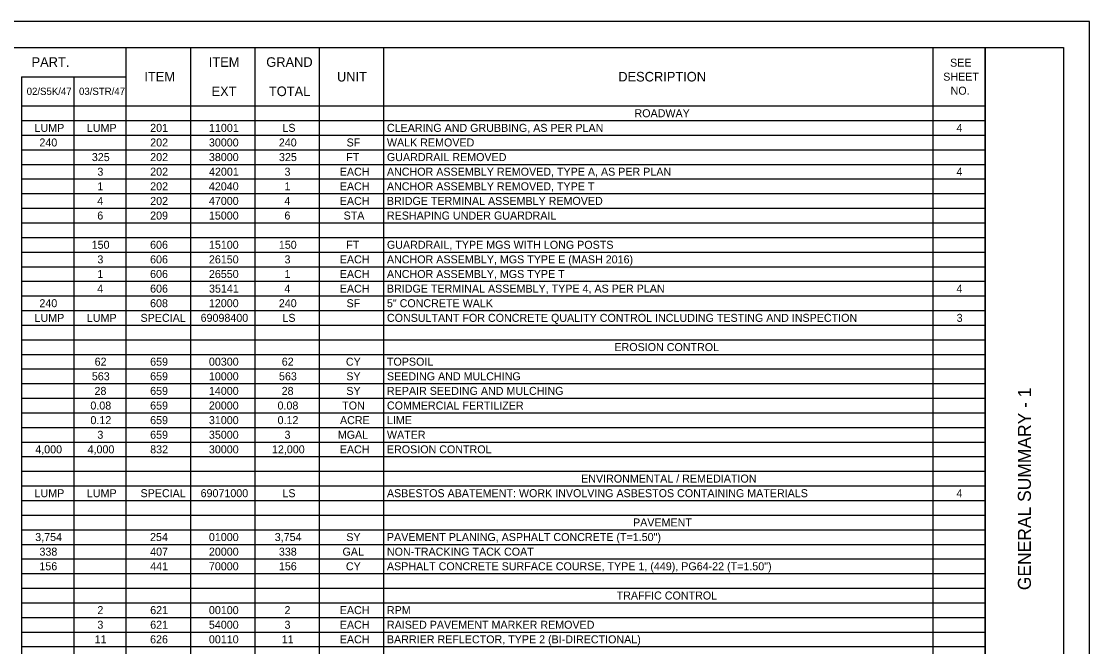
# Model space of a CAD drawing. Extents: x 0 to 34, y 0 to 22.
# Drawn here: x 13.53 to 34, y 10.02 to 22 of the extents above; entities that cross this region are included whole.
import ezdxf

# ---------------------------------------------------------------- set-up
doc = ezdxf.new("R2010")
doc.units = 0
for name, color, linetype in [('SH_Border', 7, 'Continuous'), ('SH_Cut_Line', 7, 'Continuous'), ('SH_Data', 7, 'Continuous'), ('SH_Text', 7, 'Continuous')]:
    doc.layers.add(name, color=color, linetype=linetype)

msp = doc.modelspace()

# ---------------------------------------------------------------- linework, layer by layer
at = {"layer": 'SH_Border'}
msp.add_line((32, 0.5), (32, 21.5), dxfattribs=at)
msp.add_lwpolyline([(1.5, 21.5), (33.5, 21.5), (33.5, 0.5), (1.5, 0.5)], close=True, dxfattribs=at)
at = {"layer": 'SH_Cut_Line'}
msp.add_lwpolyline([(0, 0), (34, 0), (34, 22), (0, 22)], close=True, dxfattribs=at)
at = {"layer": 'SH_Text'}
for p, q in [((13.53, 21.5), (15.535, 21.5)), ((15.535, 21.5), (32, 21.5)), ((15.535, 21.5), (15.535, 21.22)), ((16.769, 21.5), (16.769, 21.22)), ((18.003, 21.5), (18.003, 21.22)), ((19.237, 21.5), (19.237, 21.22)), ((20.471, 21.5), (20.471, 21.22)), ((30.997, 21.5), (30.997, 21.22)), ((32, 21.5), (32, 21.22)), ((15.535, 21.22), (15.535, 20.94)), ((16.769, 21.22), (16.769, 20.94)), ((18.003, 21.22), (18.003, 20.94)), ((19.237, 21.22), (19.237, 20.94)), ((20.471, 21.22), (20.471, 20.94)), ((30.997, 21.22), (30.997, 20.94)), ((32, 21.22), (32, 20.94)), ((13.53, 20.94), (15.535, 20.94)), ((13.53, 20.94), (13.53, 20.66)), ((14.533, 20.94), (14.533, 20.66)), ((15.535, 20.94), (15.535, 20.66)), ((16.769, 20.94), (16.769, 20.66)), ((18.003, 20.94), (18.003, 20.66)), ((19.237, 20.94), (19.237, 20.66)), ((20.471, 20.94), (20.471, 20.66)), ((30.997, 20.94), (30.997, 20.66)), ((32, 20.94), (32, 20.66)), ((13.53, 20.66), (13.53, 20.38)), ((14.533, 20.66), (14.533, 20.38)), ((15.535, 20.66), (15.535, 20.38)), ((16.769, 20.66), (16.769, 20.38)), ((18.003, 20.66), (18.003, 20.38)), ((19.237, 20.66), (19.237, 20.38)), ((20.471, 20.66), (20.471, 20.38)), ((30.997, 20.66), (30.997, 20.38)), ((32, 20.66), (32, 20.38)), ((13.53, 20.38), (15.535, 20.38)), ((13.53, 20.38), (13.53, 20.1)), ((14.533, 20.38), (14.533, 20.1)), ((15.535, 20.38), (32, 20.38)), ((15.535, 20.38), (15.535, 20.1)), ((16.769, 20.38), (16.769, 20.1)), ((18.003, 20.38), (18.003, 20.1)), ((19.237, 20.38), (19.237, 20.1)), ((20.471, 20.38), (20.471, 20.1)), ((30.997, 20.38), (30.997, 20.1)), ((32, 20.38), (32, 20.1)), ((13.53, 20.1), (15.535, 20.1)), ((13.53, 20.1), (13.53, 18.7)), ((14.533, 20.1), (14.533, 18.7)), ((15.535, 20.1), (32, 20.1)), ((15.535, 20.1), (15.535, 18.7)), ((16.769, 20.1), (16.769, 18.7)), ((18.003, 20.1), (18.003, 18.7)), ((19.237, 20.1), (19.237, 18.7)), ((20.471, 20.1), (20.471, 18.7)), ((30.997, 20.1), (30.997, 18.7)), ((32, 20.1), (32, 18.7)), ((13.53, 19.82), (15.535, 19.82)), ((15.535, 19.82), (32, 19.82)), ((13.53, 19.54), (15.535, 19.54)), ((15.535, 19.54), (32, 19.54)), ((13.53, 19.26), (15.535, 19.26)), ((15.535, 19.26), (32, 19.26)), ((13.53, 18.98), (15.535, 18.98)), ((15.535, 18.98), (32, 18.98)), ((13.53, 18.7), (15.535, 18.7)), ((13.53, 18.7), (13.53, 18.14)), ((14.533, 18.7), (14.533, 18.14)), ((15.535, 18.7), (32, 18.7)), ((15.535, 18.7), (15.535, 18.14)), ((16.769, 18.7), (16.769, 18.14)), ((18.003, 18.7), (18.003, 18.14)), ((19.237, 18.7), (19.237, 18.14)), ((20.471, 18.7), (20.471, 18.14)), ((30.997, 18.7), (30.997, 18.14)), ((32, 18.7), (32, 18.14)), ((13.53, 18.42), (15.535, 18.42)), ((15.535, 18.42), (32, 18.42)), ((13.53, 18.14), (15.535, 18.14)), ((13.53, 18.14), (13.53, 17.86)), ((14.533, 18.14), (14.533, 17.86)), ((15.535, 18.14), (32, 18.14)), ((15.535, 18.14), (15.535, 17.86)), ((16.769, 18.14), (16.769, 17.86)), ((18.003, 18.14), (18.003, 17.86)), ((19.237, 18.14), (19.237, 17.86)), ((20.471, 18.14), (20.471, 17.86)), ((30.997, 18.14), (30.997, 17.86)), ((32, 18.14), (32, 17.86)), ((13.53, 17.86), (15.535, 17.86)), ((13.53, 17.86), (13.53, 17.58)), ((14.533, 17.86), (14.533, 17.58)), ((15.535, 17.86), (32, 17.86)), ((15.535, 17.86), (15.535, 17.58)), ((16.769, 17.86), (16.769, 17.58)), ((18.003, 17.86), (18.003, 17.58)), ((19.237, 17.86), (19.237, 17.58)), ((20.471, 17.86), (20.471, 17.58)), ((30.997, 17.86), (30.997, 17.58)), ((32, 17.86), (32, 17.58)), ((13.53, 17.58), (15.535, 17.58)), ((13.53, 17.58), (13.53, 17.3)), ((14.533, 17.58), (14.533, 17.3)), ((15.535, 17.58), (32, 17.58)), ((15.535, 17.58), (15.535, 17.3)), ((16.769, 17.58), (16.769, 17.3)), ((18.003, 17.58), (18.003, 17.3)), ((19.237, 17.58), (19.237, 17.3)), ((20.471, 17.58), (20.471, 17.3)), ((30.997, 17.58), (30.997, 17.3)), ((32, 17.58), (32, 17.3)), ((13.53, 17.3), (15.535, 17.3)), ((13.53, 17.3), (13.53, 17.02)), ((14.533, 17.3), (14.533, 17.02)), ((15.535, 17.3), (32, 17.3)), ((15.535, 17.3), (15.535, 17.02)), ((16.769, 17.3), (16.769, 17.02)), ((18.003, 17.3), (18.003, 17.02)), ((19.237, 17.3), (19.237, 17.02)), ((20.471, 17.3), (20.471, 17.02)), ((30.997, 17.3), (30.997, 17.02)), ((32, 17.3), (32, 17.02)), ((13.53, 17.02), (15.535, 17.02)), ((13.53, 17.02), (13.53, 16.74)), ((14.533, 17.02), (14.533, 16.74)), ((15.535, 17.02), (32, 17.02)), ((15.535, 17.02), (15.535, 16.74)), ((16.769, 17.02), (16.769, 16.74)), ((18.003, 17.02), (18.003, 16.74)), ((19.237, 17.02), (19.237, 16.74)), ((20.471, 17.02), (20.471, 16.74)), ((30.997, 17.02), (30.997, 16.74)), ((32, 17.02), (32, 16.74)), ((13.53, 16.74), (15.535, 16.74)), ((13.53, 16.74), (13.53, 16.18)), ((14.533, 16.74), (14.533, 16.18)), ((15.535, 16.74), (32, 16.74)), ((15.535, 16.74), (15.535, 16.18)), ((16.769, 16.74), (16.769, 16.18)), ((18.003, 16.74), (18.003, 16.18)), ((19.237, 16.74), (19.237, 16.18)), ((20.471, 16.74), (20.471, 16.18)), ((30.997, 16.74), (30.997, 16.18)), ((32, 16.74), (32, 16.18)), ((13.53, 16.46), (15.535, 16.46)), ((15.535, 16.46), (32, 16.46)), ((13.53, 16.18), (15.535, 16.18)), ((13.53, 16.18), (13.53, 15.9)), ((14.533, 16.18), (14.533, 15.9)), ((15.535, 16.18), (32, 16.18)), ((15.535, 16.18), (15.535, 15.9)), ((16.769, 16.18), (16.769, 15.9)), ((18.003, 16.18), (18.003, 15.9)), ((19.237, 16.18), (19.237, 15.9)), ((20.471, 16.18), (20.471, 15.9)), ((30.997, 16.18), (30.997, 15.9)), ((32, 16.18), (32, 15.9)), ((13.53, 15.9), (15.535, 15.9)), ((13.53, 15.9), (13.53, 15.62)), ((14.533, 15.9), (14.533, 15.62)), ((15.535, 15.9), (32, 15.9)), ((15.535, 15.9), (15.535, 15.62)), ((16.769, 15.9), (16.769, 15.62)), ((18.003, 15.9), (18.003, 15.62)), ((19.237, 15.9), (19.237, 15.62)), ((20.471, 15.9), (20.471, 15.62)), ((30.997, 15.9), (30.997, 15.62)), ((32, 15.9), (32, 15.62)), ((13.53, 15.62), (15.535, 15.62)), ((13.53, 15.62), (13.53, 15.34)), ((14.533, 15.62), (14.533, 15.34)), ((15.535, 15.62), (32, 15.62)), ((15.535, 15.62), (15.535, 15.34)), ((16.769, 15.62), (16.769, 15.34)), ((18.003, 15.62), (18.003, 15.34)), ((19.237, 15.62), (19.237, 15.34)), ((20.471, 15.62), (20.471, 15.34)), ((30.997, 15.62), (30.997, 15.34)), ((32, 15.62), (32, 15.34)), ((13.53, 15.34), (15.535, 15.34)), ((13.53, 15.34), (13.53, 14.78)), ((14.533, 15.34), (14.533, 14.78)), ((15.535, 15.34), (32, 15.34)), ((15.535, 15.34), (15.535, 14.78)), ((16.769, 15.34), (16.769, 14.78)), ((18.003, 15.34), (18.003, 14.78)), ((19.237, 15.34), (19.237, 14.78)), ((20.471, 15.34), (20.471, 14.78)), ((30.997, 15.34), (30.997, 14.78)), ((32, 15.34), (32, 14.78)), ((13.53, 15.06), (15.535, 15.06)), ((15.535, 15.06), (32, 15.06)), ((13.53, 14.78), (15.535, 14.78)), ((13.53, 14.78), (13.53, 14.5)), ((14.533, 14.78), (14.533, 14.5)), ((15.535, 14.78), (32, 14.78)), ((15.535, 14.78), (15.535, 14.5)), ((16.769, 14.78), (16.769, 14.5)), ((18.003, 14.78), (18.003, 14.5)), ((19.237, 14.78), (19.237, 14.5)), ((20.471, 14.78), (20.471, 14.5)), ((30.997, 14.78), (30.997, 14.5)), ((32, 14.78), (32, 14.5)), ((13.53, 14.5), (15.535, 14.5)), ((13.53, 14.5), (13.53, 14.22)), ((14.533, 14.5), (14.533, 14.22)), ((15.535, 14.5), (32, 14.5)), ((15.535, 14.5), (15.535, 14.22)), ((16.769, 14.5), (16.769, 14.22)), ((18.003, 14.5), (18.003, 14.22)), ((19.237, 14.5), (19.237, 14.22)), ((20.471, 14.5), (20.471, 14.22)), ((30.997, 14.5), (30.997, 14.22)), ((32, 14.5), (32, 14.22)), ((13.53, 14.22), (15.535, 14.22)), ((13.53, 14.22), (13.53, 13.94)), ((14.533, 14.22), (14.533, 13.94)), ((15.535, 14.22), (32, 14.22)), ((15.535, 14.22), (15.535, 13.94)), ((16.769, 14.22), (16.769, 13.94)), ((18.003, 14.22), (18.003, 13.94)), ((19.237, 14.22), (19.237, 13.94)), ((20.471, 14.22), (20.471, 13.94)), ((30.997, 14.22), (30.997, 13.94)), ((32, 14.22), (32, 13.94)), ((13.53, 13.94), (15.535, 13.94)), ((13.53, 13.94), (13.53, 11.7)), ((14.533, 13.94), (14.533, 11.7)), ((15.535, 13.94), (32, 13.94)), ((15.535, 13.94), (15.535, 11.7)), ((16.769, 13.94), (16.769, 11.7)), ((18.003, 13.94), (18.003, 11.7)), ((19.237, 13.94), (19.237, 11.7)), ((20.471, 13.94), (20.471, 11.7)), ((30.997, 13.94), (30.997, 11.7)), ((32, 13.94), (32, 11.7)), ((13.53, 13.66), (15.535, 13.66)), ((15.535, 13.66), (32, 13.66)), ((13.53, 13.38), (15.535, 13.38)), ((15.535, 13.38), (32, 13.38)), ((13.53, 13.1), (15.535, 13.1)), ((15.535, 13.1), (32, 13.1)), ((13.53, 12.82), (15.535, 12.82)), ((15.535, 12.82), (32, 12.82)), ((13.53, 12.54), (15.535, 12.54)), ((15.535, 12.54), (32, 12.54)), ((13.53, 12.26), (15.535, 12.26)), ((15.535, 12.26), (32, 12.26)), ((13.53, 11.98), (15.535, 11.98)), ((15.535, 11.98), (32, 11.98)), ((13.53, 11.7), (15.535, 11.7)), ((13.53, 11.7), (13.53, 11.42)), ((14.533, 11.7), (14.533, 11.42)), ((15.535, 11.7), (32, 11.7)), ((15.535, 11.7), (15.535, 11.42)), ((16.769, 11.7), (16.769, 11.42)), ((18.003, 11.7), (18.003, 11.42)), ((19.237, 11.7), (19.237, 11.42)), ((20.471, 11.7), (20.471, 11.42)), ((30.997, 11.7), (30.997, 11.42)), ((32, 11.7), (32, 11.42)), ((13.53, 11.42), (15.535, 11.42)), ((13.53, 11.42), (13.53, 10.3)), ((14.533, 11.42), (14.533, 10.3)), ((15.535, 11.42), (32, 11.42)), ((15.535, 11.42), (15.535, 10.3)), ((16.769, 11.42), (16.769, 10.3)), ((18.003, 11.42), (18.003, 10.3)), ((19.237, 11.42), (19.237, 10.3)), ((20.471, 11.42), (20.471, 10.3)), ((30.997, 11.42), (30.997, 10.3)), ((32, 11.42), (32, 10.3)), ((13.53, 11.14), (15.535, 11.14)), ((15.535, 11.14), (32, 11.14)), ((13.53, 10.86), (15.535, 10.86)), ((15.535, 10.86), (32, 10.86)), ((13.53, 10.58), (15.535, 10.58)), ((15.535, 10.58), (32, 10.58)), ((13.53, 10.3), (15.535, 10.3)), ((13.53, 10.3), (13.53, 10.02)), ((14.533, 10.3), (14.533, 10.02)), ((15.535, 10.3), (32, 10.3)), ((15.535, 10.3), (15.535, 10.02)), ((16.769, 10.3), (16.769, 10.02)), ((18.003, 10.3), (18.003, 10.02)), ((19.237, 10.3), (19.237, 10.02)), ((20.471, 10.3), (20.471, 10.02)), ((30.997, 10.3), (30.997, 10.02)), ((32, 10.3), (32, 10.02)), ((13.53, 10.02), (15.535, 10.02)), ((13.53, 10.02), (13.53, 9.74)), ((14.533, 10.02), (14.533, 9.74)), ((15.535, 10.02), (32, 10.02)), ((15.535, 10.02), (15.535, 9.74)), ((16.769, 10.02), (16.769, 9.74)), ((18.003, 10.02), (18.003, 9.74)), ((19.237, 10.02), (19.237, 9.74)), ((20.471, 10.02), (20.471, 9.74)), ((30.997, 10.02), (30.997, 9.74)), ((32, 10.02), (32, 9.74))]:
    msp.add_line(p, q, dxfattribs=at)

# ---------------------------------------------------------------- texts
at = {"layer": 'SH_Data'}
msp.add_text('GENERAL SUMMARY - 1', height=0.25, rotation=90, dxfattribs=at).set_placement((32.875, 11.102))
at = {"layer": 'SH_Text'}
for s, height, p in [('PART.', 0.184, (13.726, 21.128)), ('ITEM', 0.184, (17.121, 21.128)), ('GRAND', 0.184, (18.223, 21.128)), ('SEE ', 0.1533, (31.326, 21.132)), ('ITEM', 0.184, (15.887, 20.848)), ('UNIT', 0.184, (19.578, 20.848)), ('DESCRIPTION', 0.184, (24.968, 20.848)), ('SHEET ', 0.1533, (31.195, 20.863)), ('02/S5K/47', 0.138, (13.632, 20.591)), ('03/STR/47', 0.138, (14.635, 20.591)), ('EXT', 0.184, (17.174, 20.568)), ('TOTAL', 0.184, (18.274, 20.568)), ('NO.', 0.1533, (31.336, 20.595)), ('ROADWAY', 0.1533, (25.279, 20.163)), ('LUMP', 0.1533, (13.783, 19.883)), ('LUMP', 0.1533, (14.786, 19.883)), ('201', 0.1533, (15.999, 19.883)), ('11001', 0.1533, (17.126, 19.883)), ('LS', 0.1533, (18.532, 19.883)), ('CLEARING AND GRUBBING, AS PER PLAN', 0.15333, (20.535, 19.883)), ('4', 0.153, (31.449, 19.883)), ('240', 0.1533, (13.876, 19.603)), ('202', 0.1533, (15.999, 19.603)), ('30000', 0.1533, (17.124, 19.603)), ('240', 0.1533, (18.464, 19.603)), ('SF', 0.1533, (19.762, 19.603)), ('WALK REMOVED', 0.15333, (20.535, 19.603)), ('325', 0.1533, (14.881, 19.323)), ('202', 0.1533, (15.999, 19.323)), ('38000', 0.1533, (17.124, 19.323)), ('325', 0.1533, (18.467, 19.323)), ('FT', 0.1533, (19.756, 19.323)), ('GUARDRAIL REMOVED', 0.15333, (20.535, 19.323)), ('3', 0.153, (14.987, 19.043)), ('202', 0.1533, (15.999, 19.043)), ('42001', 0.1533, (17.126, 19.043)), ('3', 0.153, (18.573, 19.043)), ('EACH', 0.1533, (19.632, 19.043)), ('ANCHOR ASSEMBLY REMOVED, TYPE A, AS PER PLAN', 0.15333, (20.535, 19.043)), ('4', 0.153, (31.449, 19.043)), ('1', 0.153, (14.987, 18.763)), ('202', 0.1533, (15.999, 18.763)), ('42040', 0.1533, (17.124, 18.763)), ('1', 0.153, (18.573, 18.763)), ('EACH', 0.1533, (19.632, 18.763)), ('ANCHOR ASSEMBLY REMOVED, TYPE T', 0.15333, (20.535, 18.763)), ('4', 0.153, (14.984, 18.483)), ('202', 0.1533, (15.999, 18.483)), ('47000', 0.1533, (17.124, 18.483)), ('4', 0.153, (18.57, 18.483)), ('EACH', 0.1533, (19.632, 18.483)), ('BRIDGE TERMINAL ASSEMBLY REMOVED', 0.15333, (20.535, 18.483)), ('6', 0.153, (14.985, 18.203)), ('209', 0.1533, (15.998, 18.203)), ('15000', 0.1533, (17.124, 18.203)), ('6', 0.153, (18.571, 18.203)), ('STA', 0.1533, (19.705, 18.203)), ('RESHAPING UNDER GUARDRAIL', 0.15333, (20.535, 18.203)), ('150', 0.1533, (14.878, 17.643)), ('606', 0.1533, (15.997, 17.643)), ('15100', 0.1533, (17.124, 17.643)), ('150', 0.1533, (18.464, 17.643)), ('FT', 0.1533, (19.756, 17.643)), ('GUARDRAIL, TYPE MGS WITH LONG POSTS', 0.15333, (20.535, 17.643)), ('3', 0.153, (14.987, 17.363)), ('606', 0.1533, (15.997, 17.363)), ('26150', 0.1533, (17.124, 17.363)), ('3', 0.153, (18.573, 17.363)), ('EACH', 0.1533, (19.632, 17.363)), ('ANCHOR ASSEMBLY, MGS TYPE E (MASH 2016)', 0.15333, (20.535, 17.363)), ('1', 0.153, (14.987, 17.083)), ('606', 0.1533, (15.997, 17.083)), ('26550', 0.1533, (17.124, 17.083)), ('1', 0.153, (18.573, 17.083)), ('EACH', 0.1533, (19.632, 17.083)), ('ANCHOR ASSEMBLY, MGS TYPE T', 0.15333, (20.535, 17.083)), ('4', 0.153, (14.984, 16.803)), ('606', 0.1533, (15.997, 16.803)), ('35141', 0.1533, (17.126, 16.803)), ('4', 0.153, (18.57, 16.803)), ('EACH', 0.1533, (19.632, 16.803)), ('BRIDGE TERMINAL ASSEMBLY, TYPE 4, AS PER PLAN', 0.15333, (20.535, 16.803)), ('4', 0.153, (31.449, 16.803)), ('240', 0.1533, (13.876, 16.523)), ('608', 0.1533, (15.997, 16.523)), ('12000', 0.1533, (17.124, 16.523)), ('240', 0.1533, (18.464, 16.523)), ('SF', 0.1533, (19.762, 16.523)), ('5" CONCRETE WALK', 0.15333, (20.535, 16.523)), ('LUMP', 0.1533, (13.783, 16.243)), ('LUMP', 0.1533, (14.786, 16.243)), ('SPECIAL', 0.1533, (15.814, 16.243)), ('69098400', 0.1533, (16.965, 16.243)), ('LS', 0.1533, (18.532, 16.243)), ('CONSULTANT FOR CONCRETE QUALITY CONTROL INCLUDING TESTING AND INSPECTION', 0.15333, (20.535, 16.243)), ('3', 0.153, (31.452, 16.243)), ('EROSION CONTROL', 0.15333, (24.894, 15.683)), ('62', 0.1533, (14.934, 15.403)), ('659', 0.1533, (15.998, 15.403)), ('00300', 0.1533, (17.124, 15.403)), ('62', 0.1533, (18.52, 15.403)), ('CY', 0.1533, (19.749, 15.403)), ('TOPSOIL', 0.1533, (20.535, 15.403)), ('563', 0.1533, (14.881, 15.123)), ('659', 0.1533, (15.998, 15.123)), ('10000', 0.1533, (17.124, 15.123)), ('563', 0.1533, (18.467, 15.123)), ('SY', 0.1533, (19.757, 15.123)), ('SEEDING AND MULCHING', 0.15333, (20.535, 15.123)), ('28', 0.1533, (14.932, 14.843)), ('659', 0.1533, (15.998, 14.843)), ('14000', 0.1533, (17.124, 14.843)), ('28', 0.1533, (18.518, 14.843)), ('SY', 0.1533, (19.757, 14.843)), ('REPAIR SEEDING AND MULCHING', 0.15333, (20.535, 14.843)), ('0.08', 0.1533, (14.853, 14.563)), ('659', 0.1533, (15.998, 14.563)), ('20000', 0.1533, (17.124, 14.563)), ('0.08', 0.1533, (18.439, 14.563)), ('TON', 0.1533, (19.678, 14.563)), ('COMMERCIAL FERTILIZER', 0.15333, (20.535, 14.563)), ('0.12', 0.1533, (14.854, 14.283)), ('659', 0.1533, (15.998, 14.283)), ('31000', 0.1533, (17.124, 14.283)), ('0.12', 0.1533, (18.44, 14.283)), ('ACRE', 0.1533, (19.636, 14.283)), ('LIME', 0.1533, (20.535, 14.283)), ('3', 0.153, (14.987, 14.003)), ('659', 0.1533, (15.998, 14.003)), ('35000', 0.1533, (17.124, 14.003)), ('3', 0.153, (18.573, 14.003)), ('MGAL', 0.1533, (19.594, 14.003)), ('WATER', 0.1533, (20.535, 14.003)), ('4,000', 0.1533, (13.797, 13.723)), ('4,000', 0.1533, (14.799, 13.723)), ('832', 0.1533, (15.999, 13.723)), ('30000', 0.1533, (17.124, 13.723)), ('12,000', 0.1533, (18.332, 13.723)), ('EACH', 0.1533, (19.632, 13.723)), ('EROSION CONTROL', 0.15333, (20.535, 13.723)), ('ENVIRONMENTAL / REMEDIATION', 0.15333, (24.256, 13.163)), ('LUMP', 0.1533, (13.783, 12.883)), ('LUMP', 0.1533, (14.786, 12.883)), ('SPECIAL', 0.1533, (15.814, 12.883)), ('69071000', 0.1533, (16.965, 12.883)), ('LS', 0.1533, (18.532, 12.883)), ('ASBESTOS ABATEMENT: WORK INVOLVING ASBESTOS CONTAINING MATERIALS', 0.15333, (20.535, 12.883)), ('4', 0.153, (31.449, 12.883)), ('PAVEMENT', 0.1533, (25.251, 12.323)), ('3,754', 0.1533, (13.796, 12.043)), ('254', 0.1533, (15.996, 12.043)), ('01000', 0.1533, (17.124, 12.043)), ('3,754', 0.1533, (18.385, 12.043)), ('SY', 0.1533, (19.757, 12.043)), ('PAVEMENT PLANING, ASPHALT CONCRETE (T=1.50")', 0.15333, (20.535, 12.043)), ('338', 0.1533, (13.877, 11.763)), ('407', 0.1533, (15.998, 11.763)), ('20000', 0.1533, (17.124, 11.763)), ('338', 0.1533, (18.465, 11.763)), ('GAL', 0.1533, (19.684, 11.763)), ('NON-TRACKING TACK COAT', 0.15333, (20.535, 11.763)), ('156', 0.1533, (13.876, 11.483)), ('441', 0.1533, (15.999, 11.483)), ('70000', 0.1533, (17.124, 11.483)), ('156', 0.1533, (18.465, 11.483)), ('CY', 0.1533, (19.749, 11.483)), ('ASPHALT CONCRETE SURFACE COURSE, TYPE 1, (449), PG64-22 (T=1.50")', 0.15333, (20.535, 11.483)), ('TRAFFIC CONTROL', 0.15333, (24.937, 10.923)), ('2', 0.153, (14.987, 10.643)), ('621', 0.1533, (15.999, 10.643)), ('00100', 0.1533, (17.124, 10.643)), ('2', 0.153, (18.573, 10.643)), ('EACH', 0.1533, (19.632, 10.643)), ('RPM', 0.1533, (20.535, 10.643)), ('3', 0.153, (14.987, 10.363)), ('621', 0.1533, (15.999, 10.363)), ('54000', 0.1533, (17.124, 10.363)), ('3', 0.153, (18.573, 10.363)), ('EACH', 0.1533, (19.632, 10.363)), ('RAISED PAVEMENT MARKER REMOVED', 0.15333, (20.535, 10.363)), ('11', 0.1533, (14.934, 10.083)), ('626', 0.1533, (15.997, 10.083)), ('00110', 0.1533, (17.124, 10.083)), ('11', 0.1533, (18.52, 10.083)), ('EACH', 0.1533, (19.632, 10.083)), ('BARRIER REFLECTOR, TYPE 2 (BI-DIRECTIONAL)', 0.15333, (20.535, 10.083))]:
    msp.add_text(s, height=height, dxfattribs=at).set_placement(p)

doc.saveas('drawing.dxf')
